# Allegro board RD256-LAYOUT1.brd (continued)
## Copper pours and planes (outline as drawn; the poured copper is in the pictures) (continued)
SIG00071 on BOTTOM: 8.09,4.4 8.05,4.41 8.02,4.43 6.98,5.47 6.96,5.5 6.95,5.54 6.95,10.16 6.96,10.2 6.98,10.23 7.47,10.72 7.5,10.74 7.54,10.75 9.87,10.75 9.94,10.72 9.97,10.65 9.97,10.19 9.97,10.17 10.29,9.16 11.26,8.72 11.9,8.72 11.97,8.69 12,8.62 12,8.39 11.99,8.34 11.94,8.3 11.63,8.06 11.5,7.69 11.49,7.65 11.47,7.62 10.57,6.72 10.51,6.61 10.5,6.55 10.5,4.5 10.47,4.43 10.4,4.4
SIG00072 on TOP: 7.75,3.8 7.68,3.83 7.65,3.9 7.65,4.5 7.62,4.62 7.58,4.67 7.22,5.03 7.18,5.08 7.15,5.2 7.15,6 7.18,6.12 7.28,6.22 7.4,6.25 8.2,6.25 8.27,6.22 8.3,6.15 8.3,5.57 8.33,5.44 8.37,5.39 8.74,5.03 8.76,5 8.77,4.97 8.78,4.89 8.78,3.97 8.77,3.94 8.76,3.91 8.67,3.83 8.55,3.8
VE_A on TOP: outline of 113 points within 54.95,51 78.15,61 ; 1 cut-out
VE_A on BOTTOM: 75.19,51.98 74.81,52.9 73.89,53.28 71.64,53.28 70.72,52.9 70.34,51.98 70.34,51.1 70.31,51.03 70.24,51 60.3,51 60.17,51.03 60.08,51.12 60.05,51.25 60.05,51.5 59.45,52.19 58.68,51.69 58.65,51.51 58.67,51.32 58.68,51.25 58.64,51.12 58.55,51.03 58.43,51 56.38,51 56.25,51.03 56.16,51.12 56.12,51.25 56.12,54.65 55.92,55.14 55.42,55.35 55.39,55.35 55.35,55.36 55.32,55.38 54.98,55.72 54.96,55.75 54.95,55.79 54.95,57.65 54.98,57.72 55.05,57.75 55.13,57.75 56.43,58.74 55.05,59.62 54.95,59.63 54.91,59.72 54.91,60.51 54.92,60.57 54.98,60.68 55.27,60.97 55.3,60.99 55.34,61 74.54,61 74.6,60.98 74.64,60.93 74.65,60.89 74.65,60.85 74.65,55.15 74.68,55.03 74.72,54.98 75.55,54.15 77.56,54.15 77.6,54.14 77.63,54.12 77.87,53.88 77.89,53.85 77.9,53.81 77.9,53.38 77.87,53.31 77.8,53.28 77.39,53.28 76.47,52.9 76.09,51.98 76.09,51.7 76.06,51.63 75.99,51.6 75.29,51.6 75.22,51.63 75.19,51.7 ; 1 cut-out
VE_A on CONDUCTIVE2: 71.65,53.48 70.47,52.92 70.18,51.65 70.18,51.63 70.18,51.35 70.14,51.23 70.05,51.13 69.93,51.1 68.05,51.1 67.92,51.07 67.83,50.98 67.8,50.85 67.8,47.34 67.77,47.22 67.67,47.12 67.55,47.09 46.94,47.09 40.51,48.29 34.95,51.72 34.95,51.72 33.73,52.94 33.73,52.94 31.14,56.64 29.57,60.88 29.58,60.96 29.66,61 76.05,61 76.17,60.97 76.27,60.88 76.3,60.75 76.3,58.85 77.2,57.95 78.1,58.85 78.1,60.75 78.13,60.88 78.22,60.97 78.35,61 93.84,61 93.92,60.96 93.93,60.87 94.41,57.71 97.25,56.25 98.75,56.25 98.88,56.22 98.97,56.12 99,56 99,47.19 98.97,47.12 98.9,47.09 83.75,47.09 83.62,47.12 83.53,47.22 83.5,47.34 83.5,50.85 83.47,50.98 83.38,51.07 83.25,51.1 81.39,51.1 81.27,51.13 81.17,51.23 81.14,51.35 81.14,51.98 80.7,53.04 79.64,53.48 ; 7 cut-outs
VE_B on TOP: 15.3,5.2 15.21,5.22 15.13,5.27 14.95,5.45 11.65,5.45 11.56,5.47 11.49,5.51 11.46,5.54 11.45,5.65 11.45,7.53 11.46,7.57 11.48,7.61 12.52,8.65 12.57,8.69 12.7,8.72 18.2,8.72 18.27,8.71 18.38,8.65 18.98,8.05 19.03,7.97 19.05,7.87 19.05,5.3 19.02,5.23 18.95,5.2
VE_B on BOTTOM: 25.14,7.4 25.1,7.41 25.07,7.43 24.78,7.72 24.76,7.75 24.75,7.79 24.75,8.25 24.45,8.55 22.9,8.55 22.77,8.58 22.68,8.68 22.65,8.8 22.65,10.6 22.68,10.72 22.77,10.82 22.9,10.85 26.86,10.85 26.94,10.81 26.95,10.71 27.6,9.75 28.25,10.71 28.26,10.81 28.34,10.85 32.97,10.85 33.09,10.82 33.19,10.72 33.22,10.6 33.22,8.96 33.22,8.94 33.21,8.67 33.29,8.41 33.3,8.39 33.3,8.36 33.3,7.6 33.27,7.53 33.2,7.5 28.85,7.5 28.78,7.43 28.75,7.41 28.71,7.4
VE_B on BOTTOM: 16.05,6.4 15.82,6.48 15.67,6.67 15.67,6.67 15.52,6.87 15.29,6.95 12.04,6.95 11.92,6.98 11.82,7.08 11.79,7.2 11.79,7.59 11.8,7.67 11.87,7.88 12.05,8.02 12.23,8.17 12.3,8.39 12.3,8.5 12.3,8.51 12.39,8.66 12.55,8.72 13.51,8.72 14.56,9.25 14.76,10.51 14.84,10.55 15.46,10.55 15.59,10.52 15.68,10.43 15.71,10.3 15.71,10.1 16.06,9.13 17.01,8.72 17.96,8.72 18.12,8.67 18.21,8.53 18.21,8.51 18.21,8.3 18.21,8.25 18.21,8.19 18.21,7.37 18.25,7.21 18.33,7.08 18.38,7.02 18.42,6.95 18.45,6.89 18.49,6.84 18.5,6.81 18.51,6.78 18.51,6.65 18.48,6.53 18.38,6.43 18.26,6.4
VE_B on CONDUCTIVE2: 9.66,10.9 9.73,10.87 9.76,10.8 9.76,10.02 10.18,8.98 11.21,8.52 11.31,8.52 19.21,8.52 19.26,8.52 20.14,8.81 20.69,9.56 20.69,9.56 20.76,10.01 20.69,10.47 20.69,10.5 20.69,10.8 20.72,10.87 20.79,10.9 22.75,10.9 22.88,10.93 22.97,11.03 23,11.15 23,14.8 23.03,14.87 23.1,14.9 42.9,14.9 54.19,11.06 60.79,1.13 60.77,1.04 60.69,1 6.4,1 6.28,1.03 6.19,1.12 6.15,1.25 6.15,1.42 6.16,1.44 5.49,4.42 2.75,5.75 1.25,5.75 1.12,5.78 1.03,5.88 1,6 1,14.8 1.03,14.87 1.1,14.9 7.2,14.9 7.27,14.87 7.3,14.8 7.3,10.9 ; 8 cut-outs
VL_A on BOTTOM (solid shape): 47.34,59.09 47.81,59.13 48.31,59.07 48.5,58.6 48.3,57.23 48.3,57.23 47.81,56.8 47.31,57.23 47.12,58.6 47.11,58.67

Small or netless copper shapes (teardrops, artwork), in the pictures only: 45 on TOP, 30 on BOTTOM, 1 on CONDUCTIVE3

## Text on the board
Ref Des/Silkscreen Bottom: R45 | D18 | D23 | D21 | D17 | C55 | C50 | IC5 | C19 | CN3 | C2 | IC1 | CN2 | R26 | R25 | D11 | C21 | C17 | C4 | R107 | R19 | R16 | D13 | C36 | C6 | R42 | D14 | IC2 | R41 | D10 | R2 | R8 | C15 | R24 | Q1 | C20 | C200 | R187 | D25 | D7 | R188 | D24 | R44 | C53 | C52 | C51 | R46 | R47 | C18 | D19 | C1 | R17 | C9 | R10 | Q4 | C22 | R12 | R3 | C7 | D6 | D5 | D1
Ref Des/Silkscreen Top: R59 | C60 | R50 | Q6 | IC20 | C68 | R64 | R57 | TP38 | R166 | C16 | R18 | C145 | R170 | R20 | Q3 | TP4 | R149 | Q32 | C29 | IC12 | C25 | Q26 | IC8 | R174 | C125 | R145 | R141 | TP1 | R1 | R5 | C23 | TP3 | C3 | TP13 | R36 | C31 | D9 | R37 | C41 | R38 | Q5 | IC3 | C13 | C14 | C46 | C45 | R9 | R7 | C10 | C12 | IC16 | R29 | C8 | C5 | IC4 | C49 | D15 | TP6 | TP8 | C62 | C63 | C61 | R58 | R53 | R60 | C65 | C64 | R61 | C27 | R63 | R62 | D22 | TP7 | R15 | C30 | R185 | R186 | C26 | Q2 | R11 | C34 | C32 | R40 | C33 | R39 | R32 | R23 | C11 | R6 | R13 | R4 | R14 | D4 | D2 | D3 | C42 | C44 | C43 | CN1 | R43 | T2 | IC10 | IC13 | IC9 | IC6 | T1
SYMBOL-1-TOP: 1 | 9 | 10 | 2 | RD256-1
SYMBOL-1-BOTTOM: 5 | 12 | 4 | 13 | 14 | 2 | 15 | 1 | 9 | 10
